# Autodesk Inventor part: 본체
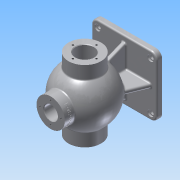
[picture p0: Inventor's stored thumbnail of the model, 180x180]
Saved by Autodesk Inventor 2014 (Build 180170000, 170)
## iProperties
Created: 2017-01
Part Number: 본체
Material: Aluminum 6061
Document SubType Name: Modeling
Designer: ksu
Density: 2.71 g/cm^3
Appearance: Aluminum - Flat
Mass: 1509 g
Surface Area: 1155.11 cm^2
Volume: 556.828 cm^3
Author: ksu
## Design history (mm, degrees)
sketch "Sketch1"
  geometry: L1 (-62.5, -57.5)-(62.5, -57.5); L2 (62.5, -57.5)-(62.5, 57.5); L3 (62.5, 57.5)-(-62.5, 57.5); L4 (-62.5, 57.5)-(-62.5, -57.5); L5 (-62.5, -57.5)-(62.5, 57.5); L6 (62.5, -57.5)-(-62.5, 57.5); 1 further point
  constraints: 12 end point, 2 midpoint, 2 parallel, 1 horizontal, 1 perpendicular
  dimensions: "d0" = 125 distance of L3.end L2.end; "d1" = 115 distance of L2.end L1.end
extrude "Extrusion1" new body sketch "Sketch1" distance "d2" = 10; taper "d3" = 0 deg
fillet "Fillet1" dims "d4" = 12
sketch "Sketch2"
  geometry: A1 r 12 centre (-50.5, -45.5) between (-62.5, -45.5) and (-50.5, -57.5) reference; A2 r 12 centre (50.5, -45.5) between (50.5, -57.5) and (62.5, -45.5) reference; A3 r 12 centre (50.5, 45.5) between (62.5, 45.5) and (50.5, 57.5) reference; A4 r 12 centre (-50.5, 45.5) between (-50.5, 57.5) and (-62.5, 45.5) reference; 5 further points
  constraints: 4 coincident
hole "Hole1" sketch "Sketch2" at (-50.5, 45.5), (50.5, 45.5), (50.5, -45.5), (-50.5, -45.5) diameter "d5" = 8; stored, may be unused: countersink angle "d9" = 90 deg, drill point angle "d11" = 118 deg; dims "d6" = 6, "d7" = 12, "d8" = 3, "d10" = 8
sketch "Sketch3"
  geometry: L1 (-50.5, 0)-(50.5, 0) reference; L2 (-50.5, 10)-(50.5, 10) reference; L3 (-87.5, 0)-(87.5, 0) reference; L4 (-62.5, 10)-(-50.5, 10) reference; L5 (-62.5, 10)-(-62.5, 0) reference; L6 (62.5, 0)-(62.5, 10) reference; L7 (0, 0)-(0, 85); L8 (-20.189, 35.996)-(20.189, 134.004); A1 r 53 centre (0, 85) between (-20.189, 35.996) and (20.189, 134.004)
  constraints: 4 end point, 2 point on circle, 1 centre point, 1 coincident, 1 midpoint, 1 parallel
  dimensions: "d12" = 85 distance of L7.start L7.end; "d13" = 106 diameter of A1
revolve "Revolution1" sketch "Sketch3" stored, may be unused: angle "d14" = 90 deg
workplane "Work Plane1"
sketch "Sketch4"
  geometry: L1 (-50.5, 0)-(50.5, 0) reference; L2 (-50.5, 10)-(50.5, 10) reference; L3 (-62.5, 10)-(-50.5, 10) reference; L4 (-62.5, 10)-(-62.5, 0) reference; L5 (62.5, 0)-(62.5, 10) reference; L6 (62.5, 0)-(50.5, 0) reference; L7 (50.5, 10)-(62.5, 10) reference; L8 (-50.5, 0)-(-62.5, 0) reference; L9 (0, 0)-(0, 85); C1 r 31 at (0, 85)
  constraints: 2 end point, 1 centre point, 1 coincident, 1 perpendicular
  dimensions: "d16" = 85 distance of L9.start L9.end; "d17" = 62 diameter of C1
extrude "Extrusion2" join sketch "Sketch4" distance "d18" = 50; taper "d19" = 0 deg
mirror "Mirror1"
workplane "Work Plane2"
sketch "Sketch5"
  geometry: C1 r 27 at (0, 0); 1 further point
  constraints: 1 centre point, 1 coincident
  dimensions: "d21" = 54 diameter of C1
extrude "Extrusion3" join sketch "Sketch5" distance "d22" = 50; taper "d23" = 0 deg
sketch "Sketch6"
  geometry: L1 (-57.5, 10)-(-45.5, 10) reference; L2 (-57.5, 0)-(-57.5, 10) reference; L3 (-45.5, 0)-(-57.5, 0) reference; L4 (45.5, 10)-(-45.5, 10) reference; L5 (45.5, 0)-(-45.5, 0) reference; L6 (57.5, 10)-(57.5, 0) reference; L7 (39.5, 10)-(51.5, 10) reference; L8 (45.5, 10)-(57.5, 10) reference; L9 (57.5, 0)-(45.5, 0) reference; L10 (-57.5, 10)-(-47.5, 10); L11 (-47.5, 10)-(-29.342, 54.942); L12 (-47.5, 10)-(0, 10); L13 (-29.342, 54.942)-(0, 54.942); L14 (0, 54.942)-(0, 10); L15 (29.342, 54.942)-(0, 54.942); L16 (47.5, 10)-(29.342, 54.942); L17 (47.5, 10)-(0, 10); 1 further point
  constraints: 16 end point, 2 symmetric about line, 1 midpoint, 1 parallel, 1 perpendicular, 1 point on line
  dimensions: "d24" = 10 distance of L1.start L10.end
extrude "Extrusion4" join sketch "Sketch6" stored distance "d26" = 8; taper "d27" = 0 deg
sketch "Sketch7"
  geometry: L1 (-62.5, 10)-(-50.5, 10) reference; L2 (50.5, 10)-(-50.5, 10) reference; L3 (50.5, 10)-(62.5, 10) reference; L4 (62.5, 10)-(62.5, 0) reference; L5 (-62.5, 0)-(-62.5, 10) reference; L6 (-62.5, 10)-(-52.5, 10); L7 (-52.5, 10)-(-52.5, 46.656); L8 (-52.5, 10)-(-28.403, 69.642); L9 (-52.5, 10)-(0, 10); L10 (0, 10)-(0, 69.642); L11 (0, 69.642)-(-28.403, 69.642); L12 (0, 69.642)-(28.403, 69.642); L13 (52.5, 10)-(28.403, 69.642); L14 (52.5, 10)-(0, 10); 1 further point
  constraints: 18 end point, 3 perpendicular, 2 symmetric about line, 1 midpoint, 1 point on line
  dimensions: "d28" = 10 distance of L1.start L6.end; "d29" = 22 deg angle of L7 L8
extrude "Extrusion5" join sketch "Sketch7" stored distance "d30" = 8; taper "d31" = 0 deg
sketch "Sketch9"
  geometry: C1 r 31 at (0, 0) reference; C2 r 17.5 at (0, 0); 1 further point
  constraints: 1 centre point, 1 coincident
  dimensions: "d35" = 35 diameter of C2
extrude "Extrusion6" cut sketch "Sketch9" stored distance "d36" = 8; taper "d37" = 0 deg
sketch "Sketch10"
  geometry: C1 r 27 at (0, 0) reference; C2 r 13 at (0, 0)
  constraints: 1 centre point, 1 coincident
  dimensions: "d38" = 26 diameter of C2
extrude "Extrusion7" cut sketch "Sketch10" distance "d39" = 50; taper "d40" = 0 deg
workplane "Work Plane3"
sketch "Sketch11"
  geometry: L1 (-27, 150)-(27, 150) reference; L2 (27, 150)-(27, 130.607) reference; L3 (-27, 150)-(-27, 130.607) reference; L4 (-27, 150)-(27, 150) reference; L5 (-27, 130.607)-(27, 130.607) reference; L6 (-27, 150)-(0, 150); L7 (0, 150)-(0, 140); L8 (0, 140)-(-27, 140); L9 (-27, 140)-(-27, 150); L10 (-20.739, 143.002)-(20.74, 143.002); L11 (20.74, 143.002)-(20.74, 136.998); L12 (20.74, 136.998)-(-20.739, 136.998); L13 (-20.739, 136.998)-(-20.739, 143.002); 2 further points
  constraints: 8 end point, 2 parallel, 1 coincident, 1 horizontal, 1 perpendicular, 2 other
  dimensions: "d42" = 10 distance of L6.end L7.end
emboss "Emboss1" sketch "Sketch11" dims "d0" = 125, "d1" = 115, "d43" = 0.5, "d44" = 0
sketch "Sketch12" dims "d45" = 45
  geometry: C1 r 31 at (0, 0) reference; 3 further points
  constraints: 1 coincident, 1 vertical alignment, 2 other
hole "Hole2" sketch "Sketch12" at (0, -22.5) diameter "d46" = 3.459; stored, may be unused: countersink angle "d50" = 90 deg, drill point angle "d52" = 118 deg; dims "d47" = 12, "d48" = 12, "d49" = 3, "d51" = 15
pattern_circular "Circular Pattern1" dims angle "d54" = 360 deg
sketch "Sketch13" dims "d56" = 48
  geometry: C1 r 31 at (0, 0) reference; 3 further points
  constraints: 1 coincident, 1 vertical alignment, 2 other
hole "Hole3" sketch "Sketch13" at (0, 24) diameter "d57" = 3.459; stored, may be unused: countersink angle "d61" = 90 deg, drill point angle "d63" = 118 deg; dims "d58" = 16, "d59" = 12, "d60" = 3, "d62" = 19
pattern_circular "Circular Pattern2" dims angle "d65" = 360 deg
sketch "Sketch14"
  geometry: L1 (68, 102.5)-(68, 67.5) reference; L2 (68, 102.5)-(-68, 102.5) reference; L3 (68, 67.5)-(-68, 67.5) reference; L4 (68, 67.5)-(52, 67.5); L5 (0, 0)-(0, 85); L6 (0, 85)-(86.046, 85); L7 (52, 67.5)-(52, 85); L8 (52, 85)-(52, 66.5); L9 (52, 66.5)-(50.25, 66.5); L10 (50.25, 66.5)-(50.25, 85); L11 (50.25, 85)-(52, 85); L12 (-52, 85)-(-52, 66.5); L13 (-52, 66.5)-(-50.25, 66.5); L14 (-50.25, 66.5)-(-50.25, 85); L15 (-50.25, 85)-(-52, 85); L16 (68, 67.5)-(-68, 67.5) reference; L17 (-68, 116)-(-68, 54) reference
  constraints: 24 end point, 4 point on line, 4 symmetric about line, 3 perpendicular, 1 collinear
  dimensions: "d67" = 16 distance of L3.start L4.end; "d68" = 85 distance of L5.start L5.end; "d69" = 90 deg angle of L5 L6; "d70" = 18.5 distance of L7.end L8.end; "d71" = 1.75 distance of L8.end L9.end; "d72" = 18.5 distance of L9.end L10.end
revolve "Revolution3" sketch "Sketch14" stored, may be unused: angle "d73" = 90 deg
sketch "Sketch15" dims "d74" = 40
  geometry: C1 r 27 at (0, 0) reference; 2 further points
  constraints: 1 coincident, 1 vertical alignment, 2 other
hole "Hole4" sketch "Sketch15" at (0, 20) diameter "d75" = 3.459; stored, may be unused: countersink angle "d79" = 90 deg, drill point angle "d81" = 118 deg; dims "d76" = 9, "d77" = 12, "d78" = 3, "d80" = 11
pattern_circular "Circular Pattern3" dims angle "d83" = 360 deg
fillet "Fillet2" dims "d85" = 3
fillet "Fillet3" dims "d86" = 3
fillet "Fillet4" dims "d87" = 3
chamfer "Chamfer1" distance "d88" = 1; stored, may be unused: second distance "d89" = 2, angle "d90" = 45 deg
sketch "Sketch16"
  geometry: L1 (0, 0)-(0, 85); L2 (0, 85)-(43, 85); L3 (43, 85)-(0, 85); L4 (0, 85)-(-43, 85); A1 r 43 centre (0, 85) between (43, 85) and (-43, 85)
  constraints: 8 end point, 2 collinear, 2 point on circle, 1 centre point, 1 coincident, 1 perpendicular, 1 vertical
  dimensions: "d91" = 85 distance of L1.start L1.end; "d92" = 86 diameter of A1
revolve "Revolution4" sketch "Sketch16" stored, may be unused: angle "d93" = 90 deg
sketch "Sketch17"
  geometry: 1 further point
body "Solid1"
node "Projected Loop1"
other parameters: "d15" = 68
